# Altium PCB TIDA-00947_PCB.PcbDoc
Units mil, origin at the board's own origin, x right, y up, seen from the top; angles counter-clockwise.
Board outline 570.71 x 413.39 mil, 2 copper layers (Top Layer, Bottom Layer), stack 62 mil thick; 18 components, 9 nets, 36 pads, 17 vias.
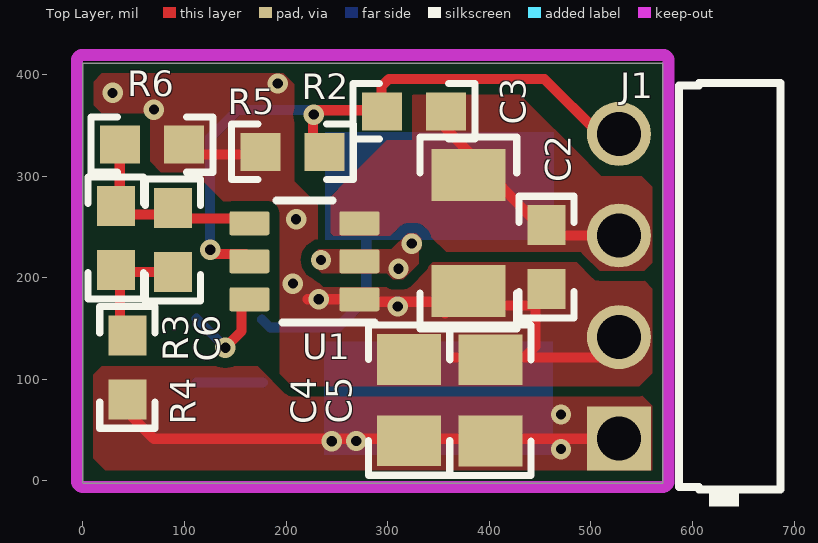
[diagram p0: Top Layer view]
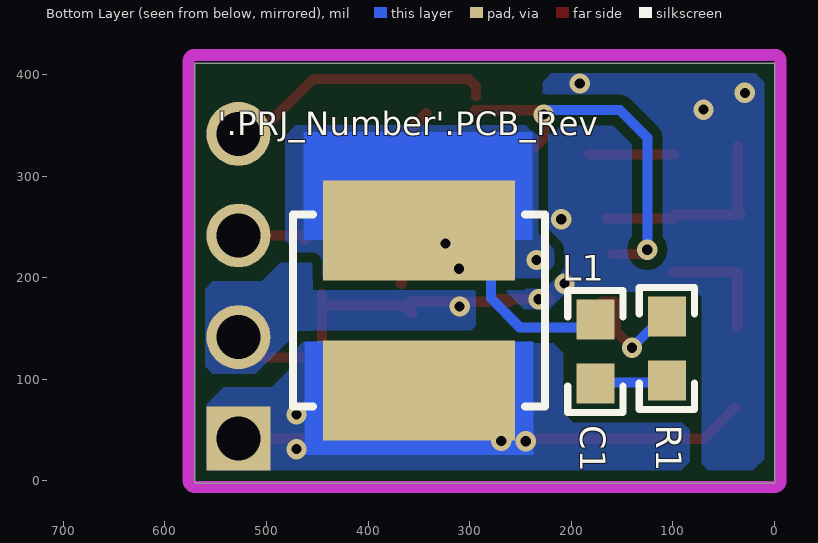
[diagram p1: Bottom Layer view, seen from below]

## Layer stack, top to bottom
Top Solder: solder mask 0.4, Solder Resist, Dk 3.5
Top Layer: signal copper 1.4
Dielectric1: core 59.2, FR-4, Dk 4.8
Bottom Layer: signal copper 1.4
Bottom Solder: solder mask 0.4, Solder Resist, Dk 3.5

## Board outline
0,-2.21 570.71,-2.21 570.71,411.18 0,411.18

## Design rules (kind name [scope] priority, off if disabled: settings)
AcuteAngle [All] p1: minimum=4.50000000000000E+0001 checktracksonly=FALSE
AssemblyTestPointUsage [All] p1: valid=2
BoardOutlineClearance BoardOutlineClearance_MountingHoles [OnCopper and InComponentClass('Mounting Holes')] p1: gap=19.68
BoardOutlineClearance BoardOutlineClearance_Poly [OnCopper and InPoly] p2: gap=10
BoardOutlineClearance [OnCopper and Not InComponentClass('Logo') and not InComponentClass('FiducialMark') and not InRegion(1000,500,4000,800)] p3: gap=10
Clearance Clearance_Keepouts [((IsTrack Or IsArc) And Not InPoly) And IsFree and IsKeepOut vs ((IsTrack Or IsArc) And Not InPoly) And IsFree and IsKeepOut] p1: gap=0
Clearance Clearance_Poly [InPolygon] p2: gap=10
Clearance [All] p3: gap=7.87
ComponentClearance ComponentClearance_MountingHoles_FiducialMarks [InComponentClass('Mounting Holes') vs InComponentClass('FiducialMark')] p1: gap=50 collisioncheckmode=3 verticalgap=10 showdistances=FALSE
ComponentClearance ComponentClearance_Shunt [InComponentClass('Header') vs InComponentClass('Shunt')] p2: gap=0 collisioncheckmode=3 verticalgap=0 showdistances=FALSE
ComponentClearance ComponentClearance_Logo [InComponentClass('Logo')] p3: gap=30 collisioncheckmode=3 verticalgap=10 showdistances=FALSE
ComponentClearance ComponentClearance_ScrewToNut [(HasFootprint('NY PMS 440 0025 PH')) vs (HasFootprint('Keystone_1902C'))] p4: gap=5 collisioncheckmode=3 verticalgap=10 showdistances=FALSE
ComponentClearance ComponentClearance_MountingHoles [InComponentClass('Mounting Holes')] p5: gap=250 collisioncheckmode=3 verticalgap=100000 showdistances=FALSE
ComponentClearance ComponentClearance_SmallPassives [HasFootprint('0201*') or HasFootprint('0402*') or HasFootprint('0508') or HasFootprint('0603*') or HasFootprint('0612') or HasFootprint('0805*') or HasFootprint('0815*') or HasFootprint('0830*') or HasFootprint('1206*') or HasFootprint('1210*') or HasFootprint('1808*') or HasFootprint('1812*') or HasFootprint('1825*') or HasFootprint('2010*') or HasFootprint('2220*') or HasFootprint('2225*') or HasFootprint('2512*') or HasFootprint('2728*') or HasFootprint('3518*') vs HasFootprint('0201*') or HasFootprint('0402*') or HasFootprint('0508') or HasFootprint('0603*') or HasFootprint('0612') or HasFootprint('0805*') or HasFootprint('0815*') or HasFootprint('0830*') or HasFootprint('1206*') or HasFootprint('1210*') or HasFootprint('1808*') or HasFootprint('1812*') or HasFootprint('1825*') or HasFootprint('2010*') or HasFootprint('2220*') or HasFootprint('2225*') or HasFootprint('2512*') or HasFootprint('2728*') or HasFootprint('3518*')] p6: gap=14.96 collisioncheckmode=3 verticalgap=10 showdistances=FALSE
ComponentClearance ComponentClearance_THtoSMT [IsThruComponent vs IsSMTComponent] p7: gap=40 collisioncheckmode=3 verticalgap=30 showdistances=FALSE
ComponentClearance ComponentClearance_THtoTH [IsThruComponent vs IsThruComponent] p8: gap=30 collisioncheckmode=3 verticalgap=30 showdistances=FALSE
ComponentClearance [All] p9: gap=30 collisioncheckmode=3 verticalgap=10 showdistances=FALSE
DiffPairsRouting [All] p1: maxlimit=100 minlimit=10 mostfreqgap=10 toplayer_minwidth=15 toplayer_maxwidth=15 toplayer_prefwidth=15 bottomlayer_minwidth=15 bottomlayer_maxwidth=15 bottomlayer_prefwidth=15 maxuncoupledlength=1000
FabricationTestPointUsage TestPointUsage [All] p1: valid=2 allowmultiple=FALSE
FabricationTestpoint Testpoint [All] p1: side=3 testpointundercomponent=TRUE minsize=40 maxsize=100 preferedsize=60 minholesize=0 maxholesize=40 preferedholesize=32 testpointgrid=1 allowsidetop=TRUE allowsidebottom=TRUE usegrid=TRUE gridtolerance=0.01
FanoutControl Fanout_LCC [IsLCC] p1: bgadir=Out bgaviamode=Centered fanoutstyle=Auto fanoutdirection=Alternating viagrid=1 // Fanout_LCC (Default Rule)
FanoutControl Fanout_BGA [IsBGA] p2: bgadir=Out bgaviamode=Centered fanoutstyle=Auto fanoutdirection=Alternating viagrid=1 // Fanout_BGA (Default Rule)
FanoutControl Fanout_Default [All] p4: bgadir=Out bgaviamode=Centered fanoutstyle=Auto fanoutdirection=Alternating viagrid=1 // Fanout_Default (Default Rule)
FanoutControl Fanout_Small [(CompPinCount < 5)] p5: bgadir=Out bgaviamode=Centered fanoutstyle=Auto fanoutdirection=OutThenIn viagrid=1 // Fanout_Small (Default Rule)
HoleSize [All] p1: absolutevalues=TRUE maxlimit=251 minlimit=7.87 maxpercent=80.000 minpercent=20.000
MinimumAnnularRing MinimumAnnularRing_ThermalPadVias [IsVia and InAnyComponent] p1: minimumring=5.91
MinimumAnnularRing [All] p2: minimumring=8
MinimumSolderMaskSliver MinimumSolderMaskSliver_Logo [InComponentClass('Logo') vs InComponentClass('Logo')] p1: minsoldermaskwidth=0.7
MinimumSolderMaskSliver [All] p2: minsoldermaskwidth=3.94
PlaneConnect [All] p1: planeconnectstyle=Direct reliefexpansion=10 reliefentries=4 reliefconductorwidth=10 reliefairgap=10
PolygonConnect [All] p1: connectstyle=Direct reliefconductorwidth=10 reliefentries=4 polygonreliefangle="90 Angle" airgapwidth=10
RoutingVias ThermalPadVias [IsVia and InAnyComponent] p1: holewidth=7.87 width=19.68 viastyle="Through Hole" minholewidth=7.87 minwidth=19.68 maxholewidth=12.99 maxwidth=23.62
RoutingVias [All] p2: holewidth=16 width=34 viastyle="Through Hole" minholewidth=7.87 minwidth=20 maxholewidth=40 maxwidth=65
SilkToBoardRegionClearance [Not ((IsComment or IsDesignator) And (Hide <> 'False')) and not InRegion(1000,500,4000,800)] p1:
SilkToSilkClearance SilkToSilkClearance_Pb-FreeLogo [(HasFootprint('Pb-Free_Overlay_Medium') OR HasFootprint('Pb-Free_Overlay_Small')) vs (HasFootprint('Pb-Free_Overlay_Medium') OR HasFootprint('Pb-Free_Overlay_Small'))] p1: silktosilkclearance=0
SilkToSilkClearance [All] p2: silktosilkclearance=4
SilkToSolderMaskClearance SilkToComponentPadClearance [IsPad and InAnycomponent] p1: minsilkscreentomaskgap=5 clearancetoexposedcopper=TRUE
SilkToSolderMaskClearance "Silk to Solder Mask Opening" [All] p2: minsilkscreentomaskgap=4 clearancetoexposedcopper=FALSE
SolderMaskExpansion [All] p1: expansion=1.97
Width [All] p1: maxlimit=100 minlimit=6 preferedwidth=10 checkconnectedcopper=TRUE
15 further rules are at their usual default settings.

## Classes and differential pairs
component class TIDA-00947_EVM_Hardware: !PCB1 ZZ2 ZZ3 ZZ4
component class TIDA-00947_SCH: C1 C2 C3 C4 C5 C6 J1 L1 R1 R2 R3 R4 R5 R6 U1
component class Header: J1
component class AssemblyNote: ZZ2 ZZ3 ZZ4

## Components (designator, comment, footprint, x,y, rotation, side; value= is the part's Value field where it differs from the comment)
C1 "GRM188R70J104KA01D" 0603 176.29,127.27 r90 bottom
C2 "885012206071" 0603 456.27,220.15 r270 top
C3 "GMK316AB7106KL" 1206 379.37,244.1 r270 top
C4 "GRM21BZ71A226ME15L" 0805_HV 321.11,79.58 r90 top
C5 "GRM21BZ71A226ME15L" 0805_HV 401.21,79.27 r90 top
C6 "GRM1885C1H300JA01D" 0603 88.66,237.2 r90 top
J1 "61300411021" Wurth_61300411021 527.66,191.51 r90 top
L1 "THPC6045MF-220M" THPC6045MF 349.85,167.94 r270 bottom
R1 "CRCW06030000Z0EA" 0603 105.95,130.26 r270 bottom
R2 "CRCW0603562KFKEA" 0603 325.99,363.75 r0 top
R3 "CRCW0603200KFKEA" 0603 32.43,239.09 r270 top
R4 "CRCW060351R0JNEA" 0603 43.81,111.75 r270 top
R5 "CRCW0603102KFKEA" 0603 206.08,323.87 r0 top
R6 "CRCW060344K2FKEA" 0603 67.93,331.09 r180 top
U1 "TPS54202DDCR" DDC0006A_N 218.04,216.11 r180 top
ZZ2 "These assemblies are ESD sensitive, ESD precautions shall be observed." AssemblyNote 185,3829.11 r0 top
ZZ3 "These assemblies must be clean and free from flux and all contaminants. Use of no clean flux is not acceptable." AssemblyNote 185,3740.56 r0 top
ZZ4 "These assemblies must comply with workmanship standards IPC-A-610 Class 2, unless otherwise specified." AssemblyNote 185,3652 r0 top

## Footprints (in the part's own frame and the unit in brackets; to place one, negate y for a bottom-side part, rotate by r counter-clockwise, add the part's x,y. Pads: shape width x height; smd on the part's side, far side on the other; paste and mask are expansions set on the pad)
0603 [mm] "0603 from SM-752 data"
  rect 1x0.95 smd: 1(-0.8,0) 2(0.8,0)
  silkscreen extent -1.52,-0.69 1.52,0.69, body extent -0.87,-0.47 0.87,0.47, height 1
0805_HV [mil] "0805 with 30mil clearance between pads"
  rect 50x63 smd: 1(-40,0) 2(40,0)
  silkscreen extent -74,-40 74,40, body extent -43,-29 43,29, height 57
1206 [mm] "1206 from SM-752 data"
  rect 1.3x1.85 smd: 1(-1.45,0) 2(1.45,0)
  silkscreen extent -2.4,-1.21 2.4,1.21, body extent -1.7,-0.9 1.7,0.9, height 1.35
AssemblyNote [mil] "Assembly Note"
DDC0006A_N [mm]
  rrect17% 1x0.6 smd: 1(-1.375,0.95) 2(-1.375,0) 3(-1.375,-0.95) 4(1.375,-0.95) 5(1.375,0) 6(1.375,0.95)
  silkscreen extent -1.75,-1.52 0.7,1.53, body extent -1.43,-1.48 1.43,1.49, height 0.92
THPC6045MF [mm] "SMD, 2-Leads, Body 6x6mm"
  rect 2.5x4.8 smd: 1(-2,0) 2(2,0)
  silkscreen extent -2.4,-3.15 2.4,3.15, body extent -3.15,-3.15 3.15,3.15, height 4.5
Wurth_61300411021 [mm] "Header, 2.54 mm, 4x1, R/A, TH"
  rect 1.6x1.6 hole 1.1: 1(-3.81,0)
  round 1.6 hole 1.1: 2(-1.27,0) 3(1.27,0) 4(3.81,0)
  silkscreen extent -5.5,-4.04 5.08,-1.5, body extent -5.08,-10.04 5.08,0.32, height 2.55

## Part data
C1: "CAP, CERM, 0.1 µF, 6.3 V, +/- 10%, X7R, 0603"
C2: "CAP, CERM, 0.1 µF, 25 V, +/- 10%, X7R, 0603"
C3: "CAP, CERM, 10 µF, 35 V, +/- 10%, X7R, 1206"
C4 C5: "CAP, CERM, 22 µF, 10 V, +/- 20%, X7R, 0805"
C6: "CAP, CERM, 30 pF, 50 V, +/- 5%, C0G/NP0, 0603"
J1: "Header, 2.54 mm, 4x1, Gold, R/A, TH"
L1: "Inductor, Ferrite, 22 µH, 1.9 A, 0.096 ohm, SMD"
R1: "RES, 0, 5%, 0.1 W, 0603"
R2: "RES, 562 k, 1%, 0.1 W, 0603"
R3: "RES, 200 k, 1%, 0.1 W, 0603"
R4: "RES, 51, 5%, 0.1 W, 0603"
R5: "RES, 102 k, 1%, 0.1 W, 0603"
R6: "RES, 44.2 k, 1%, 0.1 W, 0603"
U1: "4.5-V TO 28-V INPUT, 2-A OUTPUT, EMI FRIENDLY SYNCHRONUOUS STEP-DOWN CONVERTOR, DDC0006A"
ZZ2 ZZ3 ZZ4: library part AssemblyNote

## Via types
v1: diameter 20, hole 10, Top Layer to Bottom Layer, 17 vias

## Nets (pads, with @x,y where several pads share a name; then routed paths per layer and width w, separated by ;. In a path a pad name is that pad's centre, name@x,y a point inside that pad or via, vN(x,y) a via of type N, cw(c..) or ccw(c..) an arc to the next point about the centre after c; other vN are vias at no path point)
EN: J1.4 R2.1 R5.2 U1.5 | length 647
  Top Layer w10: v1@122.74,223.23 U1.5@159.75,223.23 ; R5.2@235.96,328.43 226.61,337.78 226.61,360.73 230.69,364.82 R2.1@294.63,364.82 ; R2.1@293.78,378.54 293.78,388.19 301.16,395.57 454.13,395.57 508.19,341.51 J1.4
  Bottom Layer w10: v1@125.14,226.15 125.14,337.81 152.34,365.01 v1@225.78,365.01 ; J1.4@527.66,338.19 J1.4 J1.4@527.66,349.73
  other v1: 125.33,227.49 227.17,360.51
GND: C2.2 C3.2 C4.2 C5.2 J1.2 R5.1 R6.1 U1.1 | length 551.9
  Top Layer w10: R6.1@98.51,321.35 R5.1@183.06,321.35 ; 221.03,178.71 U1.1 ; U1.1@260.49,176.24 C3.2@359.09,176.24 ; C3.2@356.56,164.86 364.16,172.45 C2.2@442.97,172.45 ; 363.73,121.46 434.54,121.46 ; C3.2@366.71,194.94 C3.2@367.99,193.66 ; C2.2@445.5,183.83 445.5,132.42 434.54,121.46 ; J1.2@523.04,121.46 434.54,121.46
  other v1: 309.97,171.59 232.23,178.81 206.72,194.12 209.93,257.47 69.86,365.41 29.25,381.87 191.76,391.16
NetC1_1: C1.1 R1.2 | length 65.5
  Bottom Layer w10: R1.2@111.78,96.9 C1.1@177.3,96.9
NetC1_2: C1.2 L1.1 U1.2 | length 196.4
  Bottom Layer w10: C1.2 184.13,150.93 249.68,150.93 250.03,151.28 250.8,151.28 278.95,179.43 278.95,255.25 L1.1@281.86,255.25
  other v1: 310.65,208.72 234.35,217.47 323.76,233.51
NetC6_1: C6.1 R3.2 R4.1 | length 118.1
  Top Layer w10: R4.1@36.69,151.38 36.69,205.75 C6.1@100.44,205.75
NetC6_2: C6.2 R3.1 R6.2 U1.4 | length 202.1
  Top Layer w10: R3.1@33.75,262.1 C6.2@98.66,262.1 ; R6.2@36.27,329.66 36.27,266.02 R3.1@40.48,261.8 ; C6.2@97.7,258.34 U1.4@165.28,258.34
NetR1_1: R1.1 U1.6 | length 105.6
  Top Layer w10: v1@143.31,130.3 143.31,134.53 156.23,147.45 156.23,174.79 157.67,176.24 U1.6@169.63,176.24
  Bottom Layer w10: R1.1@111.78,159.89 v1@141.33,130.34
  other v1: 140.25,131.1
VIN: C2.1 C3.1 J1.3 R2.2 U1.3 | length 245.2
  Top Layer w10: R2.2@342.79,361.8 C2.1@462.58,236.97 ; C3.1@354.12,291.77 C3.1@354.12,302.06 ; C2.1@465.78,241.51 J1.3
VOUT: C4.1 C5.1 J1.1 L1.2 R4.2 | length 501.1
  Top Layer w10: R4.2@39.22,72.15 69.85,41.51 J1.1
  other v1: 470.53,31.27 244.94,39.01 269.02,39.27 470.53,65.26

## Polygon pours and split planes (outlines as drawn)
VIN on Top Layer "Vin" (solid, remove dead copper, pour order 1): 243.79,279.64 324.23,360.09 324.23,379.57 332.23,387.57 422.64,387.57 510.45,299.76 550.06,299.76 560.57,289.26 560.57,214.97 552.48,206.89 508.58,206.89 490.18,225.29 357.46,225.29 341.58,241.17 246.42,241.17 243.79,243.8
GND on Top Layer "GND" (solid, remove dead copper, pour order 2): 504.25,196.9 552.7,196.9 561.09,188.5 561.09,106.74 547.56,93.21 206.07,93.21 193.82,105.46 193.82,204.45 196.4,207.04 220.36,207.04 236.8,190.6 259,190.6 319.9,190.6 344.52,215.22 485.93,215.22
VOUT on Top Layer "Vout" (solid, remove dead copper, pour order 3): 548.9,85.23 561.64,72.49 561.64,9.21 23.27,9.21 10.4,22.08 10.4,104.62 18.69,112.91 172,112.91 199.68,85.23
GND on Top Layer "GND2" (solid, remove dead copper, pour order 4): 235.65,193.83 231.38,198 231.38,271.56 207.96,294.98 207.96,348.86 207.96,390.19 196.91,401.24 19.04,401.24 10.69,392.9 10.69,369.87 18.7,361.86 64.41,361.86 66.11,360.15 66.11,314.45 76.72,303.84 109.6,303.84 120.38,293.06 138.03,275.41 180.73,275.41 193.76,262.38 193.76,184.07 200.32,177.52 233.61,177.52 235.65,179.56
NetC1_2 on Top Layer "SW" (solid, remove dead copper, pour order 0): 251.28,204.48 299.13,204.48 305.34,198.26 315.11,198.26 330.69,213.84 330.69,226.02 333.1,228.44 333.1,238.74 327.98,243.86 319.74,243.86 303.76,227.87 287.54,227.87 231.56,227.87 226.71,223.02 226.71,212.73 234.96,204.48
GND on Bottom Layer "GND" (solid, pour order 6): 30.03,401.33 219.31,401.33 228.35,392.29 228.35,203.01 242.02,189.34 260.63,189.33 263.79,186.17 263.79,179.85 252.65,168.71 221.97,168.71 204.32,186.37 77.18,186.37 71.76,180.95 71.76,16.66 65.38,10.28 21.52,10.28 10.35,21.44 10.35,392.56 19.13,401.33
VOUT on Bottom Layer "Vout" (solid, remove dead copper, pour order 7): 219.35,137.18 463.84,137.17 475.6,125.41 475.6,21.82 463.86,10.08 92.52,10.08 83.67,18.93 83.67,50.33 90.65,57.31 198.02,57.31 207.91,67.2 207.91,125.73
NetC1_2 on Bottom Layer "SW" (solid, remove dead copper, pour order 5): 263.03,199.46 229.58,199.46 217.03,212.01 217.03,228.09 232.79,243.85 232.79,340.68 242.12,350.01 471.15,350.01 481.76,339.39 481.76,236.59 444.83,199.66 316.09,199.66
VOUT on Bottom Layer "Vout2" (solid, remove dead copper, pour order 8): 461.24,125.96 495.13,92.07 542.1,92.07 559.15,75.02 559.15,16.29 552.8,9.93 425,9.93 399.11,35.82 399.11,89.95 434.88,125.73
GND on Bottom Layer "GND2" (solid, pour order 20): 298.72,190.57 323.99,190.57 348.12,214.7 486.5,214.7 504.81,196.39 552.84,196.39 561.16,188.07 561.16,113.37 553.05,105.26 510.91,105.26 468.55,147.62 299.32,147.61 294.25,152.68 294.25,186.1

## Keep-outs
Keep-Out Layer:
  lines w11.81: -5.91,0 ccw(c0,0) 0,-5.91 ; -5.91,0 ccw(c0,0) 0,-5.91 ; -5.91,0 -5.91,413.39 ; -5.91,413.39 cw(c0,413.39) 0,419.29 ; -5.91,413.39 cw(c0,413.39) 0,419.29 ; 0,-5.91 570.71,-5.91 ; 0,419.29 570.71,419.29 ; 570.71,-5.91 ccw(c570.71,0) 576.62,0 ; 570.71,-5.91 ccw(c570.71,0) 576.62,0 ; 570.71,419.29 cw(c570.71,413.39) 576.62,413.39 ; 570.71,419.29 cw(c570.71,413.39) 576.62,413.39 ; 576.62,0 576.62,413.39
  text ".Layer_Name" at 577,-858.49 h60

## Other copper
Top Layer:
  text ".Layer_Name" at 577,-858.49 h60
Bottom Layer:
  rectangle net NetC1_2: 238.14,237 463.61,343.14
  rectangle net VOUT: 237.28,25.35 462.74,137.33
  text ".Layer_Name" at 577,-858.49 h60

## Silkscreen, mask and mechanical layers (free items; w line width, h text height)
Top Overlay:
  text ".Layer_Name" at 577,-858.49 h60
Bottom Overlay:
  text "'.PRJ_Number'.PCB_Rev" at 547.98,332.32 h40
  text ".Layer_Name" at 577,-858.49 h60
Top Paste:
  text ".Layer_Name" at 577,-858.49 h60
Bottom Paste:
  rectangle: 238.14,226.79 463.61,343.14
  rectangle: 237.28,25.35 462.74,137.33
  text ".Layer_Name" at 577,-858.49 h60
Top Solder:
  text ".Layer_Name" at 577,-858.49 h60
  text ".Layer_Name" at 577,-858.49 h60
Bottom Solder:
  rectangle: 238.14,225.56 463.61,343.14
  rectangle: 237.28,25.35 462.74,137.33
  text ".Layer_Name" at 577,-858.49 h60
Drill Guide:
  text ".Layer_Name" at 577,-858.49 h60
M1 Board Outline:
  lines w10: 0,0 570.71,0 570.71,413.39 0,413.39 0,0
  text ".Layer_Name" at 577,-858.49 h60
M2 Board Dimensions:
  rectangle: 125,-400 500,-275
  rectangle: 0,-275 125,-150
  lines w7: 0,-275 1000,-275 ; 125,-400 125,-150 ; 250,-400 250,-150 ; 500,-400 500,-150 ; 750,-400 750,-150 ; 0,-400 0,-150 1000,-150 1000,-400 0,-400
  text ".Layer_Name" at 577,-858.49 h60
M3 3D STEP Top:
  text ".Layer_Name" at 577,-858.49 h60
M4 3D STEP Bottom:
  text ".Layer_Name" at 577,-858.49 h60
M5 Assembly Top:
  lines w10: -292,-930.17 6308,-930.17 ; -292,-726.83 6310,-726.83 ; -292,-523.5 -292,-1133.5 3713,-1133.5 6310,-1133.5 6310,-523.5 -291.5,-523.5 -291.5,-1133.5 1284,-1133.5 ; 2173,-1133.5 2173,-523.5 ; 3440,-726.83 3440,-523.5 ; 4280,-726.83 4280,-523.5 ; 4902,-1140 4902,-937.17
  text "COMPONENTS MARKED 'DNP' SHOULD NOT BE POPULATED." at 1153.5,-318.5 h60
  text "ASSEMBLY VARIANT:" at 1153,-434 h60
  text ".VariantName" at 2189,-434 h60
  text "PCB VIEWED FROM TOP SIDE" at -228.5,-655.67 h60
  text "BOARD #:" at 2248,-655.67 h60
  text ".PRJ_Number" at 2793.5,-655.67 h60
  text "REV:" at 3638,-655.67 h60
  text ".PCB_Rev" at 3929.5,-655.67 h60
  text "SVN REV:" at 4476,-655.67 h60
  text ".VersionControl_RevNumber" at 4982,-655.67 h60
  text "TID #:" at 2248,-859 h60
  text ".TID" at 2793.5,-859 h60
  text "PLOT NAME =" at -228.5,-1064.34 h60
  text ".plot_File_Name" at 577,-1064.34 h60
  text "GENERATED    :" at 2250,-1064.34 h60
  text ".Print_Date" at 3119.5,-1064.34 h60
  text ".Print_Time" at 3848.5,-1064.34 h60
  text "TEXAS INSTRUMENTS" at 5113,-1064.34 h60
M6 Assembly Bottom:
  lines w10: -292.5,-727.33 6309.5,-727.33 ; -290.5,-930.67 6309.5,-930.67 ; 1115.5,-1140.5 1115.5,-937.67 ; 1737.5,-727.33 1737.5,-524 ; 2577.5,-727.33 2577.5,-524 ; 3844.5,-1134 3844.5,-524 ; 4733.5,-1134 6309,-1134 6309,-524 -292.5,-524 -292.5,-1134 2304.5,-1134 6309.5,-1134 6309.5,-524
  text "COMPONENTS MARKED 'DNP' SHOULD NOT BE POPULATED." at 6102,-318 h60
  text ".VariantName" at 5058,-434 h60
  text "ASSEMBLY VARIANT:" at 6097,-434 h60
  text ".VersionControl_RevNumber" at 1035.5,-656.17 h60
  text "SVN REV:" at 1541.5,-656.17 h60
  text ".PCB_Rev" at 2088,-656.17 h60
  text "REV:" at 2379.5,-656.17 h60
  text ".PRJ_Number" at 3224,-656.17 h60
  text "BOARD #:" at 3769.5,-656.17 h60
  text "PCB VIEWED FROM BOTTOM SIDE" at 6246,-656.17 h60
  text ".TID" at 3224,-859.5 h60
  text "TID #:" at 3769.5,-859.5 h60
  text "TEXAS INSTRUMENTS" at 904.5,-1064.84 h60
  text ".Print_Time" at 2169,-1064.84 h60
  text ".Print_Date" at 2898,-1064.84 h60
  text "GENERATED    :" at 3767.5,-1064.84 h60
  text ".plot_File_Name" at 5440.5,-1064.84 h60
  text "PLOT NAME =" at 6246,-1064.84 h60
M9 Title Sheet:
  drawing of 57 lines, arcs and shapes, not listed
  text "1" at 739.84,8036.5 h70
  text "2" at 3235.5,8036.5 h70
  text "3" at 5724.84,8036.5 h70
  text "4" at 8231.51,8036.5 h70
  text "5" at 10730.5,8036.5 h70
  text "6" at 13235.5,8036.5 h70
  text "A" at -416.5,6893.5 h70
  text "A" at 14383.5,6893.5 h70
  text "B" at -416.5,4513.5 h70
  text "B" at 14383.5,4513.5 h70
  text "C" at -416.5,2138.5 h70
  text "C" at 14383.5,2138.5 h70
  text "PROJECT TITLE:" at 11343.5,277.5 h45
  text ".PRJ_Title" at 11393.5,144.17 h70
  text "DESIGNED FOR:" at 11343.5,-23.5 h45
  text ".PRJ_Customer" at 11393.5,-163.5 h70
  text "D" at -416.5,-231.5 h70
  text "D" at 14383.5,-231.5 h70
  text "FILE NAME:" at 11343.5,-323.5 h45
  text ".PCB_File_Name_No_Path" at 11393.5,-443.5 h70
  text "Texas Instruments (TI) and/or its licensors do not warrant the accuracy or completeness of this specification" at 6374,-605.34 h45
  text "ENGINEER:" at 11343.5,-613.5 h45
  text "LAYOUT BY:" at 12848.5,-613.5 h45
  text "or any information contained therein. TI and/or its licensors do not warrant that this design will meet" at 6329.01,-718 h45
  text ".PRJ_Engineer" at 11393.5,-768.49 h70
  text ".PCB_Layout" at 12899,-768.49 h70
  text "the specifications, will be suitable for your application or fit for any particular purpose, or will operate in" at 6329.01,-830.67 h45
  text ".Layer_Name" at 577,-858.49 h60
  text "ALTIUM DESIGNER VERSION:" at 12848.5,-923.5 h45
  text "an implementation. TI and/or its licensors do not warrant that the design is production worthy. You should" at 6329.01,-943.33 h45
  text "completely validate and test your design implementation to confirm the system functionality for your application." at 6374,-1056 h45
  text ".print_Scale" at 11393.5,-1056.83 h70
  text ".Application_BuildNumber" at 12899,-1056.83 h70
  text "1" at 739.84,-1263.5 h70
  text "2" at 3235.5,-1263.5 h70
  text "3" at 5724.84,-1263.5 h70
  text "4" at 8231.51,-1263.5 h70
  text "5" at 10730.5,-1263.5 h70
  text "6" at 13235.5,-1263.5 h70
M10 Fab Notes:
  drawing of 173 lines, arcs and shapes, not listed
  text "DESIGN INFORMATION" at 12378.02,6201 h60
  text "MIN. TRACK WIDTH:" at 11733.46,6021 h60
  text "8" at 12829.7,6021 h60
  text "MIL" at 12984.46,6021 h60
  text "MIN. CLEARANCE:" at 11733.46,5889 h60
  text "0.2" at 12769.7,5889 h60
  text "mm" at 12984.46,5889 h60
  text "MIN. VIA PAD SIZE:" at 11733.46,5757 h60
  text "24" at 12799.71,5757 h60
  text "MIL" at 12984.46,5757 h60
  text "0.05mm (2MIL)" at 12428.46,5615.29 h60
  text "MINIMUM ANNULAR RING" at 11404.23,5611 h60
  text "EXTERNAL" at 13136.46,5611 h60
  text "PER" at 11604.23,5493 h60
  text "IPC-D-275 CLASS 2 LEVEL C" at 11824.23,5493 h60
  text "MIL, HOLES" at 13312.46,5380.71 h60
  text "+/-" at 12920,5380 h60
  text "+/-" at 13774,5380 h60
  text "REGISTRATION TOLERANCES:" at 11404.23,5375 h60
  text "METAL" at 12604,5375 h60
  text "5" at 13180.2,5375 h60
  text "3" at 14013.2,5375 h60
  text "MIL" at 14129.46,5375 h60
  text "+/-" at 13774,5262 h60
  text "HOLE SIZE TOLERANCE (UNLESS OTHERWISE SPECIFIED):" at 11404.23,5257 h60
  text "3" at 14013.2,5257 h60
  text "MIL" at 14129.46,5257 h60
  text "MATERIAL:" at 11329.46,5047.54 h60
  text "FR-4 High Tg" at 12315.9,4907.21 h60
  text "FR-408" at 11750.46,4898.64 h60
  text "OTHER" at 13238.46,4898.64 h60
  text "X" at 12161,4895 h60
  text "62 MIL (1.6mm) +/-10%" at 12070.56,4735.92 h60
  text "THICKNESS:" at 11404.23,4731.64 h60
  text "X" at 11942.4,4731.64 h60
  text "OTHER" at 13355.46,4731.64 h60
  text "TOLERANCE:" at 11404.23,4573.64 h60
  text "X" at 12243.53,4573.64 h60
  text "ANSI IPC-6012 TYPE 3 CLASS 2" at 12430.48,4573.64 h60
  text "OTHER +/-" at 12430.46,4417.64 h60
  text "BOW & TWIST:" at 11404.23,4260.64 h60
  text "X" at 12243.53,4260.64 h60
  text "ANSI IPC-6012 TYPE 3 CLASS 2" at 12430.48,4260.64 h60
  text "OTHER +/-" at 12430.46,4102.13 h60
  text "DRILLING:" at 11329.46,3963.64 h60
  text "REFERENCE:" at 11404.23,3846.64 h60
  text "X" at 12052.46,3846.64 h60
  text "AS SHOWN" at 12239.46,3846.64 h60
  text "X" at 12953.46,3846.64 h60
  text "NC_DRILL FILES" at 13090.46,3846.64 h60
  text "PTH COPPER THICKNESS:" at 11404.23,3688.64 h60
  text "X" at 12534.46,3688.64 h60
  text "20-30 um" at 12671.46,3688.64 h60
  text "OTHER" at 13388.46,3688.64 h60
  text "BOARD FINISH:" at 11329.46,3529.64 h60
  text "SILKSCREEN:" at 11484.68,3411.64 h60
  text "X" at 12433.46,3411.64 h60
  text "TOP" at 12559.46,3411.64 h60
  text "X" at 12943.46,3411.64 h60
  text "BOTTOM" at 13070.46,3411.64 h60
  text "SILKSCREEN COLOR:" at 11484.68,3244.64 h60
  text "X" at 12432.42,3244.64 h60
  text "WHITE" at 12559.46,3244.64 h60
  text "OTHER" at 13070.46,3244.64 h60
  text "X" at 12563.42,3085.44 h60
  text "GREEN" at 12690.46,3085.44 h60
  text "OTHER" at 13308.46,3085.44 h60
  text "SOLDER RESIST COLOR:" at 11484.68,3074.64 h60
  text "X" at 12563.42,2915.44 h60
  text "MATTE" at 12690.46,2915.44 h60
  text "SEMI-GLOSS" at 13308,2914.8 h60
  text "IMMERSION GOLD (ENIG)" at 12390.46,2726.92 h60
  text "ENEPIG" at 13728,2723.64 h60
  text "SURFACE FINISH:" at 11329.46,2722.64 h60
  text "X" at 12203.51,2722.64 h60
  text "IMM. TIN/SILVER OR EQUIV" at 11659,2565.64 h60
  text "OTHER" at 13090.46,2565.64 h60
  text "ARRAY/PANEL:" at 11329.46,2386.64 h60
  text "CUT AND TRIM PER M1 BOARD OUTLINE" at 12390.46,2382.35 h60
  text "N.C. ROUTE" at 12390.46,2230.64 h60
  text "X" at 13069.46,2230.64 h60
  text "V. SCORE" at 13256.46,2230.64 h60
  text "CERTIFICATION:" at 11329.46,2093.64 h60
  text "MATERIALS AND WORKMANSHIP FOR ALL PCBS" at 12054.46,2093.64 h60
  text "TO MEET OR EXCEED THE REQUIREMENTS OF:" at 12054.46,1995.64 h60
  text "X" at 11680.96,1859.13 h60
  text "ANSI IPC-A-600F CLASS ->" at 11819.96,1859.13 h60
  text "X" at 13459.02,1859.13 h60
  text "2" at 13577.96,1859.14 h60
  text "1" at 13262.96,1857.64 h60
  text "3" at 13931.96,1857.64 h60
  text "X" at 12495.02,1699.64 h60
  text "RoHS" at 12631.96,1699.64 h60
  text "OTHER" at 13276.36,1699.64 h60
  text "PER ORDER" at 13673.42,1699.64 h60
  text "ALL BOARDS MUST MEET OR EXCEED UL94-V0 REQUIREMENTS." at 11357,1534 h60
  text "PCB MUST BEAR THE UL94V-0 UL REGISTERED MATERIAL ID NUMBER" at 11357,1414 h60
  text "ADDITIONAL REQUIREMENTS:" at 11329.46,1240.64 h60
  text "MICROSECTION:" at 11404.23,1125.64 h60
  text "YES" at 12309.96,1125.64 h60
  text "REQUIRED" at 13171.46,969.49 h60
  text "BARE BOARD ELEC. TEST:" at 11404.23,966.64 h60
  text "NONE" at 12709.96,966.64 h60
  text "X" at 13044.46,966.64 h60
  text "PER ORDER" at 13763.46,966.64 h60
  text ".Layer_Name" at 577,-858.49 h60
M11 Gerber Information:
  lines w10: -292,-930.17 6308,-930.17 ; -292,-726.83 6310,-726.83 ; -292,-523.5 -292,-1133.5 3713,-1133.5 6310,-1133.5 6310,-523.5 -291.5,-523.5 -291.5,-1133.5 1284,-1133.5 ; 2173,-1133.5 2173,-523.5 ; 3440,-726.83 3440,-523.5 ; 4280,-726.83 4280,-523.5 ; 4902,-1140 4902,-937.17
  text "ALL ARTWORK VIEWED FROM TOP SIDE" at -228.5,-655.67 h60
  text "BOARD #:" at 2248,-655.67 h60
  text ".PRJ_Number" at 2793.5,-655.67 h60
  text "REV:" at 3638,-655.67 h60
  text ".PCB_Rev" at 3929.5,-655.67 h60
  text "SVN REV:" at 4476,-655.67 h60
  text ".VersionControl_RevNumber" at 4982,-655.67 h60
  text "LAYER NAME =" at -228.5,-858.49 h60
  text "TID #:" at 2248,-859 h60
  text ".TID" at 2793.5,-859 h60
  text "PLOT NAME =" at -228.5,-1064.34 h60
  text ".plot_File_Name" at 577,-1064.34 h60
  text "GENERATED    :" at 2250,-1064.34 h60
  text ".Print_Date" at 3119.5,-1064.34 h60
  text ".Print_Time" at 3848.5,-1064.34 h60
  text "TEXAS INSTRUMENTS" at 5113,-1064.34 h60
M12 Stackup:
  drawing of 191 lines, arcs and shapes, not listed
  text "Layer" at 9790.34,7830 h60
  text "Name" at 10200.26,7830 h60
  text "Material" at 11130,7830 h60
  text "Thickness" at 11989.77,7830 h60
  text "Constant" at 12639.6,7830 h60
  text "Board Layer Stack" at 13209.46,7830 h60
  text "1" at 9790.34,7710 h60
  text "Top Overlay" at 10200.26,7710 h60
  text "2" at 9790.34,7590 h60
  text "Top Solder" at 10200.26,7590 h60
  text "Solder Resist" at 11130,7590 h60
  text "0.40mil" at 11989.77,7590 h60
  text "3.5" at 12639.6,7590 h60
  text "3" at 9790.34,7470 h60
  text "Top Layer" at 10200.26,7470 h60
  text "Copper" at 11130,7470 h60
  text "1.40mil" at 11989.77,7470 h60
  text "4" at 9790.34,7350 h60
  text "Dielectric1" at 10200.26,7350 h60
  text "FR-4" at 11130,7350 h60
  text "59.20mil" at 11989.77,7350 h60
  text "4.8" at 12639.6,7350 h60
  text "5" at 9790.34,7230 h60
  text "Bottom Layer" at 10200.26,7230 h60
  text "Copper" at 11130,7230 h60
  text "1.40mil" at 11989.77,7230 h60
  text "6" at 9790.34,7110 h60
  text "Bottom Solder" at 10200.26,7110 h60
  text "Solder Resist" at 11130,7110 h60
  text "0.40mil" at 11989.77,7110 h60
  text "3.5" at 12639.6,7110 h60
  text "7" at 9790.34,6990 h60
  text "Bottom Overlay" at 10200.26,6990 h60
  text ".Layer_Name" at 577,-858.49 h60
M13 Component Bodies Top:
  text ".Layer_Name" at 577,-858.49 h60
M14 Component Bodies Bottom:
  text ".Layer_Name" at 577,-858.49 h60
M15 Courtyards Top:
  text ".Layer_Name" at 577,-858.49 h60
M16 Courtyards Bottom:
  text ".Layer_Name" at 577,-858.49 h60
Drill Drawing:
  circle w10: c5363.73,3266.26 r27.63
  lines w10: 5336.1,3114.3 5391.36,3114.3 5391.36,3169.56 5336.1,3169.56 5336.1,3114.3
  lines w12: 5286,3076.99 8516.06,3076.99 ; 5286,3325.66 8516.06,3325.66 ; 5623.75,2952.66 5623.75,3450 ; 5955.56,2952.66 5955.56,3450 ; 6591.66,2952.66 6591.66,3450 ; 6850.66,2952.66 6850.66,3450 ; 7225.64,2952.66 7225.64,3450 ; 7949.86,2952.66 7949.86,3450 ; 5286,2952.66 8516.06,2952.66 8516.06,3450 5286,3450 5286,2952.66
  text "Symbol" at 5360.6,3362.97 h72
  text "Quantity" at 5661.05,3362.97 h72
  text "Finished Hole Size" at 5992.86,3362.97 h72
  text "Plated" at 6628.96,3362.97 h72
  text "Hole Type" at 6887.96,3362.97 h72
  text "Drill Layer Pair" at 7262.94,3362.97 h72
  text "Hole Tolerance" at 7987.16,3362.97 h72
  text "17" at 5661.05,3238.63 h60
  text "10.00mil (0.254mm)" at 5992.86,3238.63 h60
  text "PTH" at 6628.96,3238.63 h60
  text "Round" at 6887.96,3238.63 h60
  text "Top Layer - Bottom Layer" at 7262.94,3238.63 h60
  text "4" at 5661.05,3114.3 h60
  text "43.31mil (1.100mm)" at 5992.86,3114.3 h60
  text "PTH" at 6628.96,3114.3 h60
  text "Round" at 6887.96,3114.3 h60
  text "Top Layer - Bottom Layer" at 7262.94,3114.3 h60
  text "21 Total" at 5661.05,2989.96 h60
  text ".Layer_Name" at 577,-858.49 h60
M17 Embedded Cavity:
  text ".Layer_Name" at 577,-858.49 h60
M18 Embedded Assembly:
  text ".Layer_Name" at 577,-858.49 h60
M19 Embedded Keepout:
  text ".Layer_Name" at 577,-858.49 h60

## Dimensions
0,0 to 0,413.39 on M2 Board Dimensions
0,-400 to 1000,-400 on M2 Board Dimensions
0,0 to 570.71,0 on M2 Board Dimensions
